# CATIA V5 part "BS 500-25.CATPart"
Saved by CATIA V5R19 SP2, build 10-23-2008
Part number: BS 500-25
Bounding box of the stored display mesh (mm): x -18.951 to 18.951, y -18.952 to 18.952, z 0 to 80
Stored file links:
  C:\Users\Bora\Desktop\3D Katı model\BS serisi\BS 500\BS 500-25.CATPart
  C:\Program Files\Dassault Systemes\B19\intel_a\reffiles\standard\MetricThickPitch.txt
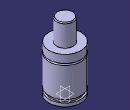
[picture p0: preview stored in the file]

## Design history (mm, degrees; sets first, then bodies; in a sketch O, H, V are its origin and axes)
Body1 (main body)
  Sketch1 on yz-plane, origin (0, 0, 0), H (0, 1, 0), V (0, 0, 1)
    point P1 (10, 79)
    point P3 (10, 79)
    point P5 (19, 44.5)
    point P6 (19, 42.5)
    point P9 (19, 44.5)
    point P14 (19, 42.5)
    line L1 (10, 79) -> (10, 54)
    arc A1 centre (9, 79) radius 1 from (10, 79) to (9, 80) ccw
    arc A2 centre (19, 43.5) radius 1 from (19, 44.5) to (19, 42.5) ccw
    line L2 (19, 0) -> (19, 4)
    line L3 (19, 44.5) -> (19, 54)
    line L4 (17, 7.5) -> (17, 4)
    line L5 (19, 7.5) -> (19, 42.5)
    line L6 (9, 80) -> (0, 80)
    point P15 (0, 80)
    line L7 (10, 54) -> (19, 54)
    line L8 (0, 0) -> (19, 0)
    line L9 (17, 7.5) -> (19, 7.5)
    line L10 (17, 4) -> (19, 4)
    coincidence: P15 V, P1 P3, P5 P9, P6 P14
    tangency: L6 A1
    horizontal: L7 H, L8 H, L9 H, L10 H
  Shaft1: profile Sketch1, axis Sketch1.V, angle 360
  Sketch2 on face of Shaft1 from Sketch1.L8, origin (0, 0, 0), H (1, 0, 0), V (0, -1, 0)
    point P1 (0, 0)
  Hole1: placed by Sketch2, at (0, 0, 0) direction (0, 0, 1), diameter 6.647, depth 4, threaded "M8", thread diameter 8, thread depth 4, pitch 1.25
